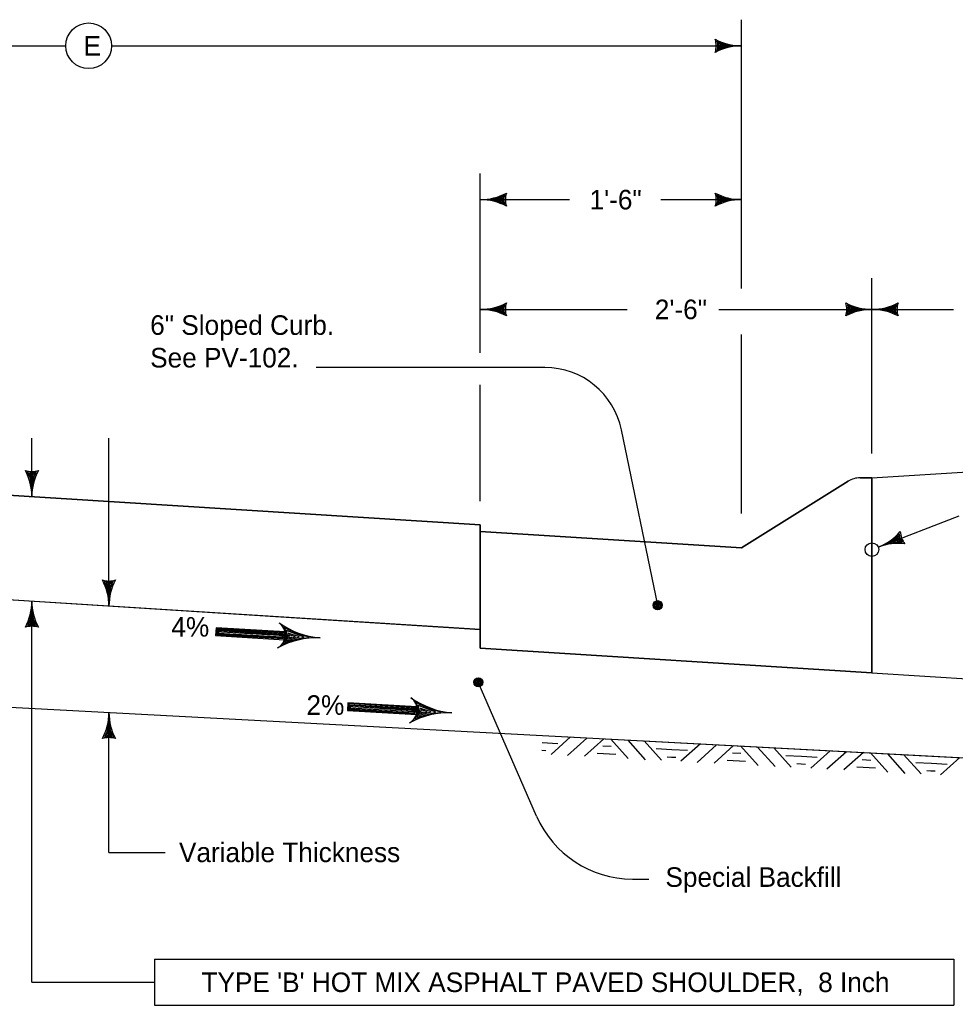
# Model space of a CAD drawing. Extents: x 10133 to 81668, y 2357 to 12713.
# Drawn here: x 11017 to 11734, y 5269 to 6024 of the extents above; entities that cross this region are included whole.
import ezdxf

# ---------------------------------------------------------------- set-up
doc = ezdxf.new("R2010")
doc.units = 0
for name, color, linetype in [('dsnStdNameDate', 7, 'Continuous'), ('dsnStdShading', 7, 'Continuous'), ('SheetAddendum', 7, 'Continuous')]:
    doc.layers.add(name, color=color, linetype=linetype)

msp = doc.modelspace()

# ---------------------------------------------------------------- linework, layer by layer
at = {"layer": 'dsnStdNameDate'}
for p, q in [((11569.95, 5818.45), (11569.95, 6024.44)), ((10569.9, 6004.44), (11052.4, 6004.44)), ((11087.4, 6004.44), (11569.9, 6004.44)), ((11569.9, 6004.44), (11550.68, 6004.44)), ((11369.94, 5769.13), (11369.94, 5906.58)), ((11369.94, 5886.58), (11438.23, 5886.58)), ((11369.94, 5886.58), (11389.16, 5886.58)), ((11508.23, 5886.58), (11569.95, 5886.58)), ((11569.95, 5886.58), (11550.73, 5886.58)), ((11669.94, 5692.15), (11669.94, 5826.43)), ((11369.94, 5802.48), (11482.54, 5802.48)), ((11369.94, 5802.48), (11389.16, 5802.48)), ((11552.54, 5802.48), (11669.94, 5802.48)), ((11669.94, 5802.48), (11650.72, 5802.48)), ((11669.94, 5802.48), (11732.38, 5802.48)), ((11669.94, 5802.48), (11689.16, 5802.48)), ((11569.95, 5646.12), (11569.95, 5783.14)), ((11419.37, 5757.98), (11244.09, 5757.98)), ((11369.94, 5655.56), (11369.94, 5744.78)), ((11505.87, 5575.83), (11478.13, 5710.12)), ((11026.42, 5659.06), (11026.42, 5703.91)), ((11085.45, 5575.18), (11085.45, 5703.91)), ((11026.42, 5659.06), (11026.42, 5678.28)), ((11674.79, 5620.34), (11736.68, 5644.41)), ((11674.79, 5620.34), (11692.71, 5627.31)), ((11085.45, 5575.18), (11085.45, 5594.4)), ((11026.42, 5286.95), (11026.42, 5578.9)), ((11026.42, 5578.9), (11026.42, 5559.68)), ((11220.27, 5552.42), (11167.31, 5555.53)), ((11220.29, 5555.62), (11220.29, 5555.62)), ((11219.99, 5549.43), (11219.99, 5549.43)), ((11413.06, 5414.11), (11368.38, 5516.8)), ((11321.28, 5495.02), (11268.32, 5498.14)), ((11321.31, 5498.23), (11321.31, 5498.23)), ((11085.45, 5386.28), (11085.45, 5493.6)), ((11085.45, 5493.6), (11085.45, 5474.38)), ((11321, 5492.03), (11321, 5492.03)), ((11085.45, 5386.28), (11128.61, 5386.28)), ((11486.42, 5366.02), (11499.14, 5366.02)), ((11026.42, 5286.95), (11120.32, 5286.95))]:
    msp.add_line(p, q, dxfattribs=at)
for points in [[(11551.08, 6008), (11551.8, 6004.42), (11551.05, 6000.82), (11555.35, 6002.89), (11562.17, 6004.42), (11554.83, 6006.14), (11551.68, 6007.55), (11552.46, 6004.42), (11552.16, 6002.11), (11554.98, 6003.46), (11558.77, 6004.42), (11554.74, 6005.6), (11552.64, 6006.32), (11553.03, 6003.25), (11555.83, 6004.42), (11553.63, 6005.11), (11553.6, 6004.06), (11554.62, 6004.39)], [(11388.77, 5883.02), (11388.04, 5886.6), (11388.8, 5890.2), (11384.5, 5888.13), (11377.68, 5886.6), (11385.01, 5884.88), (11388.17, 5883.47), (11387.38, 5886.6), (11387.68, 5888.91), (11384.86, 5887.56), (11381.07, 5886.6), (11385.1, 5885.42), (11387.2, 5884.7), (11386.81, 5887.77), (11384.02, 5886.6), (11386.21, 5885.91), (11386.24, 5886.96), (11385.22, 5886.63)], [(11551.12, 5890.14), (11551.84, 5886.56), (11551.09, 5882.96), (11555.39, 5885.03), (11562.21, 5886.56), (11554.88, 5888.28), (11551.72, 5889.69), (11552.5, 5886.56), (11552.2, 5884.25), (11555.03, 5885.6), (11558.81, 5886.56), (11554.79, 5887.74), (11552.68, 5888.46), (11553.07, 5885.39), (11555.87, 5886.56), (11553.67, 5887.26), (11553.64, 5886.2), (11554.67, 5886.53)], [(11388.77, 5798.92), (11388.04, 5802.5), (11388.8, 5806.1), (11384.5, 5804.03), (11377.68, 5802.5), (11385.01, 5800.78), (11388.17, 5799.37), (11387.38, 5802.5), (11387.68, 5804.81), (11384.86, 5803.46), (11381.07, 5802.5), (11385.1, 5801.33), (11387.2, 5800.6), (11386.81, 5803.67), (11384.02, 5802.5), (11386.21, 5801.81), (11386.24, 5802.86), (11385.22, 5802.53)], [(11651.11, 5806.04), (11651.83, 5802.47), (11651.08, 5798.86), (11655.38, 5800.93), (11662.2, 5802.47), (11654.87, 5804.18), (11651.71, 5805.59), (11652.5, 5802.47), (11652.19, 5800.15), (11655.02, 5801.5), (11658.81, 5802.47), (11654.78, 5803.64), (11652.68, 5804.36), (11653.07, 5801.29), (11655.86, 5802.47), (11653.67, 5803.16), (11653.64, 5802.1), (11654.66, 5802.44)], [(11688.77, 5798.92), (11688.04, 5802.5), (11688.8, 5806.1), (11684.5, 5804.03), (11677.68, 5802.5), (11685.01, 5800.78), (11688.17, 5799.37), (11687.38, 5802.5), (11687.68, 5804.81), (11684.86, 5803.46), (11681.07, 5802.5), (11685.1, 5801.33), (11687.2, 5800.6), (11686.81, 5803.67), (11684.02, 5802.5), (11686.21, 5801.81), (11686.24, 5802.86), (11685.22, 5802.53)], [(11029.98, 5677.89), (11026.4, 5677.17), (11022.8, 5677.92), (11024.87, 5673.62), (11026.4, 5666.8), (11028.12, 5674.13), (11029.53, 5677.29), (11026.4, 5676.51), (11024.09, 5676.81), (11025.44, 5673.98), (11026.4, 5670.2), (11027.57, 5674.22), (11028.3, 5676.33), (11025.23, 5675.94), (11026.4, 5673.14), (11027.09, 5675.33), (11026.04, 5675.36), (11026.37, 5674.34)], [(11693.63, 5623.84), (11691.66, 5626.92), (11691.06, 5630.55), (11687.8, 5627.06), (11682, 5623.16), (11689.45, 5624.22), (11692.91, 5624.05), (11691.05, 5626.68), (11690.49, 5628.94), (11688.35, 5626.66), (11685.16, 5624.39), (11689.34, 5624.76), (11691.57, 5624.85), (11690.09, 5627.56), (11687.91, 5625.46), (11690.2, 5625.61), (11689.85, 5626.6), (11689.02, 5625.92)], [(11089.01, 5594.01), (11085.44, 5593.28), (11081.83, 5594.04), (11083.91, 5589.74), (11085.44, 5582.92), (11087.15, 5590.25), (11088.56, 5593.4), (11085.44, 5592.62), (11083.12, 5592.92), (11084.48, 5590.1), (11085.44, 5586.31), (11086.61, 5590.34), (11087.33, 5592.44), (11084.27, 5592.05), (11085.44, 5589.26), (11086.13, 5591.45), (11085.08, 5591.48), (11085.41, 5590.46)], [(11505.6, 5572.62), (11506.78, 5573.15), (11508.61, 5573.72), (11508.97, 5575.58), (11508.72, 5577.22), (11507.54, 5578.73), (11505.8, 5578.58), (11503.95, 5578.32), (11503.07, 5576.85), (11502.91, 5575.3), (11503.99, 5573.27), (11505.34, 5573.11), (11507.18, 5573.57), (11508.69, 5574.75), (11508.64, 5576.5), (11507.46, 5577.9), (11505.81, 5578.06), (11503.97, 5577.7), (11503.69, 5576.66), (11503.32, 5575.42), (11504.18, 5573.9), (11505.52, 5573.94), (11507.06, 5574.19), (11508.16, 5575.04), (11507.6, 5576.57), (11506.45, 5577.46), (11504.9, 5577.52), (11504.51, 5576.69), (11504.03, 5575.75), (11504.78, 5574.53), (11505.92, 5574.26), (11506.94, 5574.8), (11507.01, 5575.93), (11506.47, 5576.74), (11505.43, 5577.02), (11504.93, 5576.59), (11504.64, 5575.97), (11505.18, 5575.06), (11505.9, 5574.87), (11506.61, 5575.31), (11506.49, 5575.92), (11505.97, 5576.32), (11505.25, 5576.29), (11505.26, 5575.78), (11505.89, 5575.49)], [(11022.86, 5560.08), (11026.43, 5560.8), (11030.04, 5560.05), (11027.97, 5564.34), (11026.43, 5571.17), (11024.72, 5563.83), (11023.31, 5560.68), (11026.43, 5561.46), (11028.75, 5561.16), (11027.4, 5563.98), (11026.43, 5567.77), (11025.26, 5563.74), (11024.54, 5561.64), (11027.61, 5562.03), (11026.43, 5564.83), (11025.74, 5562.63), (11026.8, 5562.6), (11026.46, 5563.62)], [(11220.34, 5555.42), (11167.48, 5558.53), (11167.13, 5552.54), (11219.99, 5549.43), (11220.12, 5554.57), (11168.13, 5557.82), (11167.98, 5553.05), (11218.87, 5550.26), (11219.21, 5553.82), (11168.81, 5556.99), (11168.75, 5553.8), (11218.24, 5550.89), (11218.51, 5553.14), (11169.37, 5556.29), (11169.33, 5554.5), (11217.63, 5551.73)], [(11219.14, 5559.4), (11221.18, 5555.7), (11221.14, 5550.46), (11218.95, 5546.01), (11226.95, 5548.79), (11236.23, 5550.9), (11238.85, 5551.34), (11232.31, 5553.05), (11222.91, 5556.93), (11220.16, 5558.61), (11220.56, 5547.44), (11234.93, 5551.37), (11221.42, 5556.35), (11221.49, 5548.64), (11231.36, 5551.65), (11222.63, 5554.35), (11221.97, 5549.94), (11228.24, 5551.57), (11223.62, 5553.17), (11223.23, 5551.07), (11225.52, 5551.59)], [(11368.65, 5520.01), (11367.47, 5519.48), (11365.64, 5518.91), (11365.28, 5517.05), (11365.53, 5515.41), (11366.71, 5513.9), (11368.46, 5514.05), (11370.3, 5514.31), (11371.18, 5515.78), (11371.35, 5517.33), (11370.26, 5519.36), (11368.91, 5519.52), (11367.07, 5519.06), (11365.56, 5517.88), (11365.62, 5516.13), (11366.79, 5514.73), (11368.44, 5514.57), (11370.28, 5514.93), (11370.56, 5515.97), (11370.94, 5517.21), (11370.07, 5518.73), (11368.73, 5518.69), (11367.2, 5518.44), (11366.09, 5517.59), (11366.65, 5516.06), (11367.81, 5515.17), (11369.35, 5515.11), (11369.74, 5515.94), (11370.23, 5516.88), (11369.47, 5518.1), (11368.33, 5518.37), (11367.32, 5517.83), (11367.25, 5516.7), (11367.78, 5515.89), (11368.82, 5515.61), (11369.32, 5516.04), (11369.62, 5516.66), (11369.07, 5517.57), (11368.35, 5517.76), (11367.64, 5517.32), (11367.76, 5516.71), (11368.29, 5516.31), (11369.01, 5516.34), (11368.99, 5516.85), (11368.37, 5517.14)], [(11321.36, 5498.02), (11268.5, 5501.13), (11268.15, 5495.14), (11321, 5492.03), (11321.13, 5497.17), (11269.14, 5500.43), (11269, 5495.66), (11319.89, 5492.86), (11320.23, 5496.43), (11269.83, 5499.59), (11269.77, 5496.41), (11319.26, 5493.5), (11319.52, 5495.74), (11270.38, 5498.89), (11270.34, 5497.1), (11318.64, 5494.33)], [(11320.16, 5502.01), (11322.2, 5498.3), (11322.15, 5493.06), (11319.97, 5488.61), (11327.96, 5491.39), (11337.25, 5493.5), (11339.87, 5493.94), (11333.33, 5495.66), (11323.93, 5499.53), (11321.17, 5501.22), (11321.58, 5490.04), (11335.95, 5493.97), (11322.43, 5498.95), (11322.51, 5491.25), (11332.38, 5494.25), (11323.65, 5496.96), (11322.99, 5492.55), (11329.26, 5494.17), (11324.64, 5495.77), (11324.25, 5493.67), (11326.54, 5494.2)], [(11081.89, 5474.77), (11085.47, 5475.5), (11089.08, 5474.74), (11087, 5479.04), (11085.47, 5485.86), (11083.76, 5478.53), (11082.35, 5475.38), (11085.47, 5476.16), (11087.78, 5475.86), (11086.43, 5478.68), (11085.47, 5482.47), (11084.3, 5478.44), (11083.58, 5476.34), (11086.64, 5476.73), (11085.47, 5479.52), (11084.78, 5477.33), (11085.83, 5477.3), (11085.5, 5478.32)]]:
    msp.add_lwpolyline(points, dxfattribs=at)
for centre, radius in [((11069.9, 6004.44), 17.5), ((11505.87, 5575.83), 3.5), ((11368.38, 5516.8), 3.5)]:
    msp.add_circle(centre, radius, dxfattribs=at)
for centre, radius, start, end in [((11534.27, 6004.44), 16.42, 342.26665, 17.73335), ((11569.9, 6046.94), 42.5, 241.92751, 270), ((11569.9, 5961.94), 42.5, 90, 118.07249), ((11369.94, 5929.08), 42.5, 270, 298.07249), ((11405.57, 5886.58), 16.42, 162.26665, 197.73335), ((11534.31, 5886.58), 16.42, 342.26665, 17.73335), ((11569.95, 5929.08), 42.5, 241.92751, 270), ((11369.94, 5844.08), 42.5, 61.92751, 90), ((11569.95, 5844.08), 42.5, 90, 118.07249), ((11369.94, 5844.98), 42.5, 270, 298.07249), ((11405.57, 5802.48), 16.42, 162.26665, 197.73335), ((11634.3, 5802.48), 16.42, 342.26665, 17.73335), ((11669.94, 5844.98), 42.5, 241.92751, 270), ((11669.94, 5844.98), 42.5, 270, 298.07249), ((11705.57, 5802.48), 16.42, 162.26665, 197.73335), ((11369.94, 5759.98), 42.5, 61.92751, 90), ((11669.94, 5759.98), 42.5, 90, 118.07249), ((11669.94, 5759.98), 42.5, 61.92751, 90), ((11419.37, 5697.98), 60, 11.67017, 90), ((11026.42, 5694.7), 16.42, 252.26665, 287.73335), ((10983.92, 5659.06), 42.5, 360, 28.07249), ((11068.92, 5659.06), 42.5, 151.92751, 180), ((11659.39, 5659.95), 42.5, 291.24881, 319.3213), ((11708.01, 5633.25), 16.42, 183.51546, 218.98216), ((11690.2, 5580.73), 42.5, 83.17632, 111.24881), ((11085.45, 5610.81), 16.42, 252.26665, 287.73335), ((11042.95, 5575.18), 42.5, 360, 28.07249), ((11127.95, 5575.18), 42.5, 151.92751, 180), ((10983.92, 5578.9), 42.5, 331.92751, 360), ((11068.92, 5578.9), 42.5, 180, 208.07249), ((11026.42, 5543.27), 16.42, 72.26665, 107.73335), ((11209.3, 5553.06), 11.29, 298.34846, 54.91909), ((11252.85, 5615.06), 64.48, 234.91951, 264.94954), ((11245.28, 5486.39), 64.48, 88.318, 118.34803), ((11310.32, 5495.67), 11.29, 298.34846, 54.91909), ((11353.86, 5557.67), 64.48, 234.91951, 264.94954), ((11042.95, 5493.6), 42.5, 331.92751, 360), ((11127.95, 5493.6), 42.5, 180, 208.07249), ((11346.29, 5428.99), 64.48, 88.318, 118.34803), ((11085.45, 5457.97), 16.42, 72.26665, 107.73335), ((11486.42, 5446.02), 80, 203.51102, 270)]:
    msp.add_arc(centre, radius, start, end, dxfattribs=at)
at = {"layer": 'dsnStdShading'}
for p, q in [((11369.94, 5637.44), (10569.91, 5687.93)), ((11669.94, 5673.45), (11660.81, 5673.45)), ((11669.94, 5523.97), (11669.94, 5673.45)), ((11651.81, 5670.87), (11569.95, 5619.76)), ((11369.94, 5557.28), (11369.94, 5637.44)), ((11569.95, 5619.76), (11369.94, 5632.38)), ((11369.94, 5632.38), (11369.94, 5542.91)), ((10569.91, 5607.77), (11369.94, 5557.28)), ((11369.94, 5542.91), (11669.94, 5523.97))]:
    msp.add_line(p, q, dxfattribs=at)
msp.add_arc((11660.81, 5656.45), 17, 90, 121.97497, dxfattribs=at)
at = {"layer": 'SheetAddendum'}
for p, q in [((10569.91, 5687.87), (11369.94, 5637.39)), ((11660.81, 5673.45), (11669.94, 5673.45)), ((11669.94, 5673.45), (11669.94, 5523.97)), ((11569.95, 5619.76), (11651.81, 5670.87)), ((11369.94, 5637.39), (11369.94, 5557.23)), ((11369.94, 5542.91), (11369.94, 5632.38)), ((11369.94, 5632.38), (11569.95, 5619.76)), ((11369.94, 5557.23), (10569.9, 5607.71)), ((11669.94, 5523.97), (11369.94, 5542.91)), ((10399.67, 5529.86), (11417.55, 5476.04)), ((11669.94, 5523.97), (11869.94, 5511.35)), ((11417.55, 5476.04), (11869.94, 5452.13)), ((11439.13, 5474.9), (11424.26, 5461.53)), ((11451.55, 5474.02), (11436.68, 5460.64)), ((11464.55, 5473.56), (11449.68, 5460.18)), ((11469.96, 5473.27), (11483.33, 5458.41)), ((11482.94, 5472.36), (11496.31, 5457.49)), ((11495.38, 5471.93), (11508.76, 5457.06)), ((11538.54, 5469.65), (11523.67, 5456.27)), ((11550.96, 5468.77), (11536.1, 5455.39)), ((11563.97, 5468.3), (11549.1, 5454.93)), ((11569.37, 5468.02), (11582.75, 5453.15)), ((11582.35, 5467.11), (11595.72, 5452.24)), ((11594.79, 5466.67), (11608.17, 5451.81)), ((11637.96, 5464.39), (11623.09, 5451.02)), ((11650.38, 5463.51), (11635.51, 5450.13)), ((11663.38, 5463.05), (11648.51, 5449.67)), ((11668.78, 5462.76), (11682.16, 5447.89)), ((11681.76, 5461.85), (11695.14, 5446.98)), ((11694.21, 5461.42), (11707.58, 5446.55)), ((11737.37, 5459.14), (11722.5, 5445.76)), ((11120.32, 5304.59), (11732.69, 5304.59)), ((11120.32, 5304.59), (11120.32, 5269.31)), ((11732.69, 5304.59), (11732.69, 5269.31)), ((11120.32, 5269.31), (11732.69, 5269.31))]:
    msp.add_line(p, q, dxfattribs=at)
for points in [[(11669.93, 5673.42), (11869.94, 5686.04)], [(11417.55, 5476.04), (11869.94, 5452.13)], [(11417.26, 5470.58), (11429.27, 5469.94)], [(11463.7, 5468.1), (11470.23, 5467.75)], [(11416.95, 5464.79), (11420.22, 5464.61)], [(11459.57, 5462.45), (11473.74, 5461.7)], [(11504.66, 5465.96), (11516.67, 5465.32)], [(11513.1, 5459.7), (11516.36, 5459.53)], [(11516.67, 5465.32), (11528.69, 5464.69)], [(11563.12, 5462.84), (11569.64, 5462.5)], [(11604.07, 5460.7), (11616.09, 5460.07)], [(11616.09, 5460.07), (11628.1, 5459.43)], [(11516.37, 5459.53), (11519.63, 5459.36)], [(11558.98, 5457.2), (11573.16, 5456.45)], [(11612.52, 5454.45), (11615.78, 5454.28)], [(11615.78, 5454.28), (11619.04, 5454.1)], [(11662.53, 5457.59), (11669.05, 5457.24)], [(11703.49, 5455.45), (11715.5, 5454.81)], [(11715.5, 5454.81), (11727.51, 5454.18)], [(11658.4, 5451.94), (11672.57, 5451.19)], [(11711.93, 5449.19), (11715.19, 5449.02)], [(11715.19, 5449.02), (11718.46, 5448.85)]]:
    msp.add_lwpolyline(points, dxfattribs=at)
msp.add_circle((11669.94, 5618.45), 5.21, dxfattribs=at)
msp.add_arc((11660.81, 5656.45), 17, 90, 121.97497, dxfattribs=at)

# ---------------------------------------------------------------- texts
at = {"layer": 'dsnStdNameDate'}
for s, p in [('E', (11065.98, 5996.94)), ('1\'-6"', (11453.65, 5879.08)), ('2\'-6"', (11503.65, 5794.98)), ('6" Sloped Curb.', (11117.03, 5782.98)), ('See PV-102.', (11117.03, 5757.98)), ('4%', (11133.28, 5551.77)), ('2%', (11236.8, 5491.84)), ('Variable Thickness', (11139.09, 5378.99)), ('Special Backfill', (11511.75, 5360.04)), ("TYPE 'B' HOT MIX ASPHALT PAVED SHOULDER,  8 Inch", (11156.33, 5279.45))]:
    msp.add_text(s, height=15, dxfattribs=at).set_placement(p)

doc.saveas('drawing.dxf')
